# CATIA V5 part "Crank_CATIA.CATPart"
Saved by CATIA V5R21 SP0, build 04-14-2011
Part number: Crank
Bounding box of the stored display mesh (mm): x -8 to 50, y -6 to 10, z 0 to 10
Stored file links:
  C:\Users\DHARUN\Documents\Codex\2026-11-26\task-2-structural-simulation-fea-perform\outputs\task3_slider_crank\Crank_CATIA.CATPart
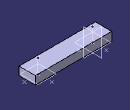
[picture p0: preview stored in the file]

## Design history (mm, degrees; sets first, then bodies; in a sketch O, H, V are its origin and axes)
Set1 "KinematicReferences"
  Point1 "O": (0, 0, 0)
  Point2 "Z": (0, 0, 10)
  Point3 "X": (10, 0, 0)
  Point4 "Y": (0, 10, 0)
  Line1: type PtPt, FirstPoint Point1, SecondPoint Point2
  Plane1: type 3Points, Element1 Point1, Element2 Point3, Element3 Point4
  Point5 "PinO": (40, 0, 0)
  Point6 "PinZ": (40, 0, 10)
  Point7 "PinX": (50, 0, 0)
  Point8 "PinY": (40, 10, 0)
  Line2: type PtPt, FirstPoint Point5, SecondPoint Point6
  Plane2: type 3Points, Element1 Point5, Element2 Point7, Element3 Point8
Body1 (main body)
  Sketch1 on xy-plane, origin (0, 0, 0), H (1, 0, 0), V (0, 1, 0)
    line L1 (-8, -6) -> (48, -6)
    line L2 (48, -6) -> (48, 6)
    line L3 (48, 6) -> (-8, 6)
    line L4 (-8, 6) -> (-8, -6)
    point P1 (-8, -6)
    point P2 (48, -6)
    point P3 (48, -6)
    point P4 (48, 6)
    point P5 (48, 6)
    point P6 (-8, 6)
    point P7 (-8, 6)
    point P8 (-8, -6)
    coincidence: P1 P8, P2 P3, P4 P5, P6 P7
  Pad1 "Crank_Solid": profile Sketch1, direction (0, 0, 1), length 6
